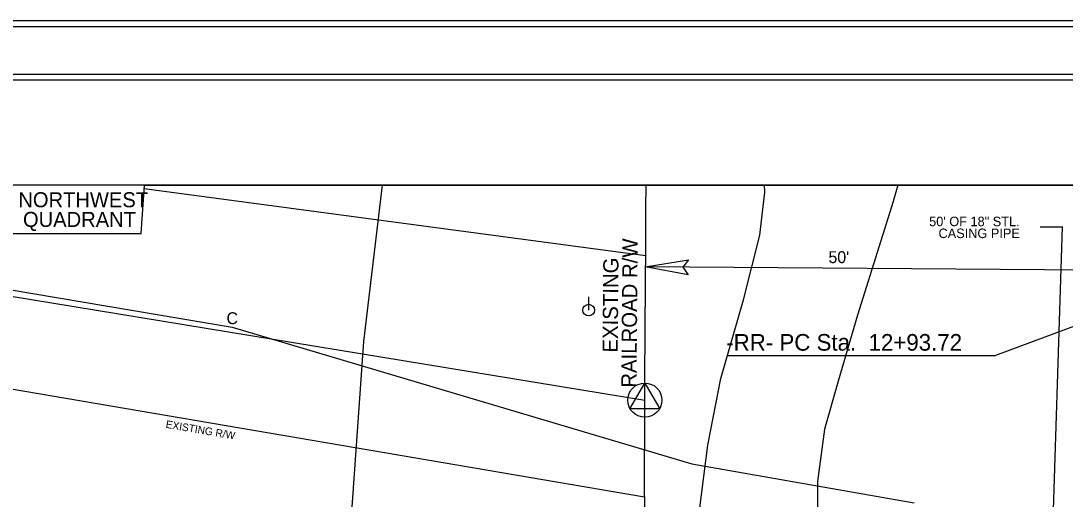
# Model space of a CAD drawing. Extents: x 1756964 to 1757438, y 736785 to 737067.
# Drawn here: x 1757019.9 to 1757129.6, y 737016.7 to 737067 of the extents above; entities that cross this region are included whole.
import ezdxf

# ---------------------------------------------------------------- set-up
doc = ezdxf.new("R2010")
doc.units = 0
for name, color, linetype in [('Exist Right of Way Line', 7, 'Continuous'), ('Exist Right of Way Line Text', 7, 'Continuous'), ('Exist Right of Way Width CELL', 7, 'Continuous'), ('Exist Roads Soil', 7, 'Continuous'), ('Exist Utilities Gas UG Line SUE LOS B', 7, 'Continuous'), ('Exist Utilities Power Pole CELL', 7, 'Continuous'), ('Exist Utilities Sanitary Sewer UG Line Text', 7, 'Continuous'), ('Old_Level_18', 7, 'Continuous'), ('Old_Level_3', 7, 'Continuous'), ('Old_Level_62', 7, 'Continuous'), ('Old_Level_63', 7, 'Continuous'), ('Prop Easement Permanent Utility', 7, 'Continuous'), ('Prop ROW Marker CELL', 7, 'Continuous'), ('Prop ROW RW Lines', 7, 'Continuous'), ('Prop SS Cut Line', 7, 'Continuous'), ('Prop SS Cut Text', 7, 'Continuous'), ('Sheet Plan CELL', 7, 'Continuous'), ('Sheet Plot Border Inside CELL', 7, 'Continuous'), ('Sheet Plot Border Outside CELL', 7, 'Continuous')]:
    doc.layers.add(name, color=color, linetype=linetype)

msp = doc.modelspace()

# ---------------------------------------------------------------- linework, layer by layer
at = {"layer": 'Exist Right of Way Line'}
for p, q in [((1757085.4, 737016.95), (1757085.47, 737036.89)), ((1757018.66, 737028.35), (1757085.4, 737016.95)), ((1757085.4, 737016.95), (1757085.19, 736956.11))]:
    msp.add_line(p, q, dxfattribs=at)
msp.add_arc((1762390.7, 737018.29), 5305.26, 179.66052, 179.79908, dxfattribs=at)
at = {"layer": 'Exist Right of Way Width CELL'}
msp.add_line((1757135.49, 737040.75), (1757085.49, 737041.12), dxfattribs=at)
msp.add_lwpolyline([(1757089.99, 737040.31), (1757085.49, 737041.12), (1757090.02, 737041.88), (1757089.44, 737041.09)], close=True, dxfattribs=at)
at = {"layer": 'Exist Roads Soil'}
for points in [[(1757083.43, 737001.33), (1757085.98, 737003.4), (1757088.01, 737005.93), (1757089.29, 737008.39), (1757091.19, 737015.5), (1757092.04, 737022.38), (1757093.41, 737029.38), (1757095.79, 737037.65), (1757097.52, 737044.48), (1757098.05, 737048.99), (1757098, 737049.72)], [(1757112.01, 737049.72), (1757111.51, 737048.01), (1757107.77, 737036.06), (1757105.75, 737029.1), (1757104.33, 737024.05), (1757103.59, 737018.56), (1757103.61, 737013.19), (1757104.75, 737009.2), (1757106.35, 737005.59), (1757108.73, 737002.4), (1757110.73, 736999.93), (1757114.7, 736996.45)]]:
    msp.add_lwpolyline(points, dxfattribs=at)
at = {"layer": 'Exist Utilities Gas UG Line SUE LOS B'}
msp.add_lwpolyline([(1757057.85, 737049.72), (1757055.88, 737033.29), (1757054.62, 737015.36), (1757053.46, 737004.02), (1757052.43, 736991.98), (1757053, 736981.13), (1757053.5, 736968.56), (1757053.85, 736952.9), (1757054.08, 736941.32), (1757054.32, 736926.61), (1757054.29, 736924.98)], dxfattribs=at)
at = {"layer": 'Exist Utilities Power Pole CELL'}
for q in [(1757079.54, 737037.98), (1757079.54, 737036.58)]:
    msp.add_line((1757079.54, 737036.58), q, dxfattribs=at)
msp.add_circle((1757079.54, 737036.58), 0.613, dxfattribs=at)
at = {"layer": 'Exist Utilities Sanitary Sewer UG Line Text'}
msp.add_line((1757126.96, 737045.35), (1757129.31, 737045.35), dxfattribs=at)
msp.add_lwpolyline([(1757127.79, 736996.85), (1757129.31, 737045.35)], dxfattribs=at)
at = {"layer": 'Old_Level_18'}
msp.add_lwpolyline([(1757032.86, 737049.72), (1757243.29, 737049.72), (1757243.29, 737044.26), (1757256.72, 737044.26), (1757256.72, 736930.25), (1757242.38, 736930.25), (1757242.38, 736924.98), (1757033.35, 736924.98), (1757033.35, 736930.17), (1757018.66, 736930.17), (1757018.66, 737044.64), (1757032.53, 737044.64)], close=True, dxfattribs=at)
at = {"layer": 'Old_Level_3'}
for p in [(1757135.47, 737036.72), (1757094.16, 737031.82)]:
    msp.add_line(p, (1757122.27, 737031.82), dxfattribs=at)
at = {"layer": 'Old_Level_62'}
msp.add_lwpolyline([(1756969.89, 736798.25), (1757382.39, 736798.25), (1757382.39, 737060.75), (1756969.89, 737060.75)], close=True, dxfattribs=at)
at = {"layer": 'Old_Level_63'}
msp.add_lwpolyline([(1757388.64, 737067), (1756963.64, 737067), (1756963.64, 736792), (1757388.64, 736792)], close=True, dxfattribs=at)
at = {"layer": 'Prop Easement Permanent Utility'}
msp.add_line((1757032.84, 737049.39), (1757085.5, 737042.32), dxfattribs=at)
at = {"layer": 'Prop ROW Marker CELL'}
msp.add_line((1757085.44, 737027.12), (1757085.44, 737027.12), dxfattribs=at)
msp.add_lwpolyline([(1757083.88, 737026.22), (1757085.44, 737028.92), (1757087, 737026.22)], close=True, dxfattribs=at)
msp.add_circle((1757085.44, 737027.12), 1.8, dxfattribs=at)
at = {"layer": 'Prop ROW RW Lines'}
msp.add_line((1757018.66, 737038.09), (1757085.44, 737027.12), dxfattribs=at)
at = {"layer": 'Prop SS Cut Line'}
for p, q in [((1757018.66, 737038.75), (1757042.08, 737034.79)), ((1757042.08, 737034.79), (1757090.39, 737020.43)), ((1757090.39, 737020.43), (1757113.74, 737016.31))]:
    msp.add_line(p, q, dxfattribs=at)
at = {"layer": 'Sheet Plan CELL'}
for points in [[(1757382.4, 737060.75), (1757007.39, 737060.75), (1757007.39, 736798.25), (1757382.39, 736798.25)], [(1757256.72, 737049.72), (1757018.66, 737049.72), (1757018.66, 736924.98), (1757256.72, 736924.98)]]:
    msp.add_lwpolyline(points, close=True, dxfattribs=at)
at = {"layer": 'Sheet Plot Border Inside CELL'}
msp.add_lwpolyline([(1756969.02, 736797.62), (1757385.52, 736797.62), (1757385.52, 737061.37), (1756969.02, 737061.37)], close=True, dxfattribs=at)
at = {"layer": 'Sheet Plot Border Outside CELL'}
msp.add_lwpolyline([(1756965.77, 736792.62), (1757386.64, 736792.62), (1757386.64, 737066.37), (1756965.77, 737066.37)], close=True, dxfattribs=at)

# ---------------------------------------------------------------- texts
at = {"layer": 'Exist Right of Way Line Text'}
for s, height, rotation, p in [('RAILROAD R/W', 1.6, 89.5215, (1757084.56, 737028.42)), ('EXISTING ', 1.6, 89.5215, (1757082.59, 737032.12)), ('EXISTING R/W', 0.8, 350.3067, (1757035.06, 737024.22))]:
    msp.add_text(s, height=height, rotation=rotation, dxfattribs=at).set_placement(p)
at = {"layer": 'Exist Right of Way Width CELL'}
msp.add_text("50'", height=1.25, rotation=360, dxfattribs=at).set_placement((1757104.73, 737041.53))
at = {"layer": 'Exist Utilities Sanitary Sewer UG Line Text'}
for s, p in [('50\' OF 18" STL.', (1757115.31, 737045.41)), ('CASING PIPE', (1757116.29, 737044.16))]:
    msp.add_text(s, height=1, rotation=360, dxfattribs=at).set_placement(p)
at = {"layer": 'Old_Level_3'}
msp.add_text('-RR- PC Sta.  12+93.72', height=1.75, rotation=360, dxfattribs=at).set_placement((1757093.99, 737032.32))
at = {"layer": 'Prop SS Cut Text'}
msp.add_text('C', height=1.25, rotation=360, dxfattribs=at).set_placement((1757041.49, 737035.11))
at = {"layer": 'Sheet Plan CELL'}
for s, p in [('NORTHWEST', (1757019.62, 737047.4)), ('QUADRANT', (1757020.11, 737045.33))]:
    msp.add_text(s, height=1.582, rotation=360, dxfattribs=at).set_placement(p)

doc.saveas('drawing.dxf')
